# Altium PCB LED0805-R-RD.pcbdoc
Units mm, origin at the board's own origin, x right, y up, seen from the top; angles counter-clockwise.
Board outline 16.92 x 14.76 mm, 2 copper layers (Top Layer, Bottom Layer); 1 components, 0 nets, 2 pads, 0 vias.
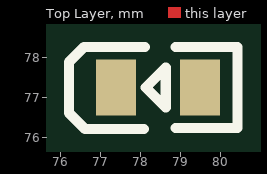
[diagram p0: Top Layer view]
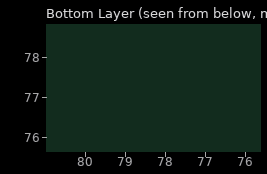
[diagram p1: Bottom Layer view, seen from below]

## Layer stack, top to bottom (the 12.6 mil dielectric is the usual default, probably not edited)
Top Layer: signal copper (thickness not stored)
Dielectric: dielectric 0.32, FR-4, Dk 4.8
Bottom Layer: signal copper (thickness not stored)

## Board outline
86.766,69.85 69.85,69.85 69.85,84.607 86.766,84.607

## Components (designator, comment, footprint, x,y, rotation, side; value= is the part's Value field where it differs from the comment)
? "LED0805-R-RD" LED0805-R-RD 78.424,77.243 r0 top

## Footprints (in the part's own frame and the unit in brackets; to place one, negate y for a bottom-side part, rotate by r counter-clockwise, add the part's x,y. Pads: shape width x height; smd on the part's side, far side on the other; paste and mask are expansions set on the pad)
LED0805-R-RD [mm]
  rect 1x1.4 smd: 1(1.05,0) 2(-1.05,0)
  silkscreen extent -2.22,-1.04 1.99,1.01

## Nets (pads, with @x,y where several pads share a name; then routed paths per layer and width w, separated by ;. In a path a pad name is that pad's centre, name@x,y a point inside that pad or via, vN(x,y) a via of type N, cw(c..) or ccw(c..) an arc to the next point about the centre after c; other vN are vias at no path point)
pads on no net: ?.1 ?.2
